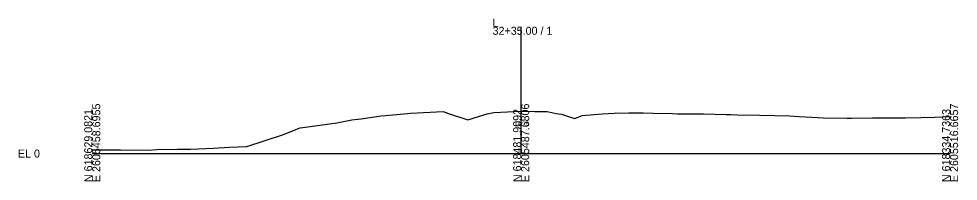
# Model space of a CAD drawing. Extents: x -26 to 2605155, y -10 to 618566.
# Drawn here: x 5874.3 to 6202.8, y -9.7 to 47.2 of the extents above; entities that cross this region are included whole.
import ezdxf

# ---------------------------------------------------------------- set-up
doc = ezdxf.new("R2010")
doc.units = 0
for name, color, linetype in [('Exist Cross Section Cell', 7, 'Continuous'), ('Exist XS Center Line Elevation Label', 7, 'Continuous'), ('Exist XS Ground Line', 7, 'Continuous')]:
    doc.layers.add(name, color=color, linetype=linetype)

msp = doc.modelspace()

# ---------------------------------------------------------------- linework, layer by layer
at = {"layer": 'Exist Cross Section Cell'}
for p, q in [((6050, 0), (6050, 44.37)), ((5900, 0), (6050, 0)), ((6050, 0), (6200, 0))]:
    msp.add_line(p, q, dxfattribs=at)
at = {"layer": 'Exist XS Ground Line'}
msp.add_lwpolyline([(5900, 1.24), (5900.33, 1.26), (5906.75, 1.28), (5908.84, 1.29), (5909.26, 1.28), (5909.87, 1.26), (5919.45, 1.22), (5922.56, 1.38), (5929.64, 1.53), (5934.39, 1.53), (5942.35, 1.92), (5948.04, 2.19), (5954.02, 2.49), (5966.54, 6.51), (5972.76, 8.99), (5973.6, 9.08), (5985.48, 10.72), (5990.79, 11.79), (5994, 12.18), (6000.99, 13.15), (6002.51, 13.29), (6010.25, 14), (6011.27, 14.09), (6022.73, 14.68), (6024.64, 14.04), (6031.3, 11.83), (6036.96, 13.51), (6038.16, 13.89), (6040.45, 14.32), (6045.23, 14.55), (6049.81, 14.79), (6054.74, 14.71), (6059.07, 14.66), (6062.23, 14.05), (6064.12, 13.74), (6067.2, 12.77), (6068.7, 12.31), (6069.54, 12.64), (6071.32, 13.29), (6078.35, 13.88), (6082.52, 14.16), (6087.66, 14.19), (6092.71, 14.21), (6096.18, 14.15), (6102.91, 13.98), (6104.69, 13.95), (6113.21, 13.89), (6113.75, 13.88), (6121.72, 13.66), (6123.29, 13.65), (6125.63, 13.6), (6133.48, 13.43), (6138.75, 13.29), (6143.67, 13.14), (6147.27, 12.96), (6153.87, 12.66), (6155.78, 12.52), (6164.06, 12.43), (6165.5, 12.43), (6172.81, 12.44), (6174.25, 12.44), (6181.33, 12.45), (6184.44, 12.5), (6189.84, 12.61), (6194.64, 12.73), (6200, 12.95)], dxfattribs=at)

# ---------------------------------------------------------------- texts
at = {"layer": 'Exist Cross Section Cell'}
for s, p in [('L', (6040, 44.37)), ('32+35.00 / 1', (6040, 41.57)), ('EL 0', (5874, -1.4))]:
    msp.add_text(s, height=2.8, dxfattribs=at).set_placement(p)
for s, p in [('E 2605458.6955', (5902.8, -10)), ('E 2605487.6806', (6052.8, -10)), ('E 2605516.6657', (6202.8, -10)), ('N 618629.0821', (5900, -10)), ('N 618481.9092', (6050, -10)), ('N 618334.7363', (6200, -10))]:
    msp.add_text(s, height=2.8, rotation=90, dxfattribs=at).set_placement(p)
at = {"layer": 'Exist XS Center Line Elevation Label'}
msp.add_text('14.79', height=1.5, dxfattribs=at).set_placement((6047.57, 9.79))

doc.saveas('drawing.dxf')
